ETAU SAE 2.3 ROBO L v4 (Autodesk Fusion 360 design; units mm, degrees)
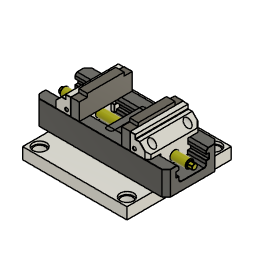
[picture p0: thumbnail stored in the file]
base_feature "Base Feature1" OffsetX 0 OffsetY 0 OffsetZ 0 OffsetX 0 OffsetY 0 OffsetZ 0 OffsetX 0 OffsetY 0 OffsetZ 0 OffsetX 0 OffsetY 0 OffsetZ 0
base_feature "Base Feature1" OffsetX 0 OffsetY 0 OffsetZ 0 OffsetX 0 OffsetY 0 OffsetZ 0 OffsetX 0 OffsetY 0 OffsetZ 0 OffsetX 0 OffsetY 0 OffsetZ 0
work_plane "WorkPlane2" User Parameter 100 named "Ouverture"
base_feature "Base Feature1"
position "Position1"
sketch "Sketch1" plane through (9.1729, 31.8972, 315) normal (1, 0, 0) x axis (0, 1, 0)
work_axis "WorkAxis1"
work_point "WorkPoint1"
joint_origin "JointOrigin7" OffsetX 0 OffsetY 0 OffsetZ 0
work_point "WorkPoint2"
work_point "WorkPoint1"
position "Position2"
position "Position3"
joint_origin "JointOrigin8" OffsetX 0 OffsetY 0 OffsetZ 0
position "Position4"
ground "Terre5"
position "Position5"
ground "Terre6"
position "Position6" TranslateAlongZ -50 (= "-Ouverture / 2") TranslateAlongZ 50 (= "Ouverture / 2")
as_built_joint "Réelle"
sketch "Esquisse1" plane through (0, 0, 0) normal (0, 0, 1) x axis (1, 0, 0)
  line L1 (-62.5, 29) -> (62.5, 29)
  line L2 (-62.5, -29) -> (-62.5, 29)
  line L3 (62.5, -29) -> (-62.5, -29)
  line L4 (62.5, 29) -> (62.5, -29)
  line L5 (-62.5, -29) -> (62.5, 29)
  line L6 (62.5, -29) -> (-62.5, 29)
  point P6 (0, 0)
  point P1 (0, 0)
  point P3 (-62.5, 29)
  point P4 (-62.5, -29)
  horizontal L1
  perpendicular L1 L2
  parallel L1 L3
  parallel L2 L4
  coincident L5 P6
  coincident L6 P6
  coincident P1 P6
  dimension "d1_1" distance P3 P4 = 58
  dimension "d2_1" distance L2 L4 = 125
extrude "Extrusion1" new body sketch "Esquisse1" profile of L1 L2 L3 L4 along normal blind 20 named "d3_1"
sketch "Esquisse2" plane through (0, -29, 0) normal (0, -1, 0) x axis (1, 0, 0)
  line L1 (62.5, 0) -> (-62.5, 0)
  line L2 (62.5, 20) -> (62.5, 0)
  line L3 (-62.5, 20) -> (62.5, 20)
  line L4 (-62.5, 0) -> (-62.5, 20)
  line L5 (-32.5, 26.5) -> (32.5, 26.5)
  line L6 (-32.5, 13.5) -> (-32.5, 26.5)
  line L7 (32.5, 13.5) -> (-32.5, 13.5)
  line L8 (32.5, 26.5) -> (32.5, 13.5)
  line L9 (-32.5, 13.5) -> (32.5, 26.5)
  line L10 (32.5, 13.5) -> (-32.5, 26.5)
  point P10 (0, 20)
  horizontal L5
  perpendicular L5 L6
  parallel L5 L7
  parallel L6 L8
  coincident L9 P10
  coincident L10 P10
  midpoint L3 P10
  dimension "d5_1" distance L6 L8 = 65
  dimension "d6_1" distance L5 L7 = 13
extrude "Extrusion2" add sketch "Esquisse2" profile of L3 L6 L7 L8 along normal blind 7 named "d7_1"
extrude "Extrusion3" cut of existing geometry blind -7
sketch "Esquisse3" plane through (0, 22, 0) normal (0, 1, 0) x axis (-1, 0, 0)
  line L1 (62.5, 0) -> (-62.5, 0)
  line L2 (62.5, 20) -> (62.5, 0)
  line L3 (-62.5, 20) -> (62.5, 20)
  line L4 (-62.5, 0) -> (-62.5, 20)
  line L5 (-43.5, 0) -> (-43.5, 20)
  line L6 (43.5, 20) -> (43.5, 0)
  point P6 (-43.5, 20)
  point P7 (-43.5, 0)
  point P8 (43.5, 0)
  point P9 (43.5, 20)
  coincident L3 P6
  coincident L1 P7
  perpendicular L1 L5
  coincident L1 P8
  coincident L3 P9
  perpendicular L3 L6
  dimension "d11" distance L4 L5 = 19
  dimension "d12" distance L2 L6 = 19
extrude "Extrusion4" cut sketch "Esquisse3" against normal blind 11
sketch "Esquisse4" plane through (0, 0, 20) normal (0, 0, 1) x axis (-1, 0, 0)
  line L1 (-43.5, -11) -> (-62.5, -11)
  line L2 (-43.5, -22) -> (-43.5, -11)
  line L3 (43.5, -22) -> (-43.5, -22)
  line L4 (43.5, -11) -> (43.5, -22)
  line L5 (62.5, -11) -> (43.5, -11)
  line L6 (62.5, 29) -> (62.5, -11)
  line L7 (32.5, 29) -> (62.5, 29)
  line L8 (32.5, 36) -> (32.5, 29)
  line L9 (-32.5, 36) -> (32.5, 36)
  line L10 (-32.5, 29) -> (-32.5, 36)
  line L11 (-62.5, 29) -> (-32.5, 29)
  line L12 (-62.5, -11) -> (-62.5, 29)
  line L13 (-62.5, 8.3) -> (62.5, 8.3)
  circle C1 centre (35.175, 8.3) radius 3.4
  circle C2 centre (-35.175, 8.3) radius 3.4
  point P14 (62.5, 8.3)
  point P15 (-62.5, 8.3)
  point P16 (35.175, 8.3)
  point P17 (-35.175, 8.3)
  point P18 (0, 8.3)
  point P19 (35.175, 8.3)
  point P20 (-35.175, 8.3)
  coincident L6 P14
  perpendicular L6 L13
  coincident L12 P15
  coincident L13 P16
  coincident L13 P17
  midpoint L13 P18
  coincident P16 P19
  coincident P17 P20
  dimension "d15_1" distance L7 L13 = 20.7
  dimension "d16_1" distance P16 P18 = 35.175
  dimension "d17_1" distance P16 P17 = 70.35
  dimension "d18_1" diameter C1 = 6.8
  dimension "d19_1" diameter C2 = 6.8
extrude "Extrusion5" cut sketch "Esquisse4" profile of L13 C1 C2 against normal blind 10 named "d20_1"
copy_paste_bodies "Copier/Coller des corps"
move "Déplacer1"
sketch "Esquisse5" plane through (0, 0, 0) normal (1, 0, 0) x axis (0, 1, 0)
sketch "Esquisse6" plane through (0, 22, 0) normal (0, 1, 0) x axis (-1, 0, 0)
  line L1 (-43.5, 0) -> (-43.5, 20)
  line L2 (43.5, 0) -> (-43.5, 0)
  line L3 (43.5, 20) -> (43.5, 0)
  line L4 (-43.5, 20) -> (43.5, 20)
sketch "Esquisse7" plane through (0, 22, 0) normal (0, 1, 0) x axis (-1, 0, 0)
  line L1 (43.5, 50) -> (43.5, 30)
  line L2 (-43.5, 50) -> (43.5, 50)
  line L3 (-43.5, 30) -> (-43.5, 50)
  line L4 (43.5, 30) -> (-43.5, 30)
sketch "Esquisse8" plane through (0, 11, 0) normal (0, 1, 0) x axis (-1, 0, 0)
  line L1 (-62.5, 0) -> (-62.5, 20)
  line L2 (-43.5, 0) -> (-62.5, 0)
  line L3 (-43.5, 20) -> (-43.5, 0)
  line L4 (-62.5, 20) -> (-43.5, 20)
sketch "Esquisse9" plane through (0, 11, 0) normal (0, 1, 0) x axis (-1, 0, 0)
  line L1 (62.5, 20) -> (62.5, 0)
  line L2 (43.5, 20) -> (62.5, 20)
  line L3 (43.5, 0) -> (43.5, 20)
  line L4 (62.5, 0) -> (43.5, 0)
sketch "Esquisse10" plane through (43.5, 0, 0) normal (1, 0, 0) x axis (0, 1, 0)
  line L1 (22, 20) -> (22, 0)
  line L2 (11, 20) -> (22, 20)
  line L3 (11, 0) -> (11, 20)
  line L4 (22, 0) -> (11, 0)
  line L5 (11, 50.006) -> (11, 0)
  point P5 (11, 0)
  point P6 (11, 0)
  coincident P5 P6
  perpendicular L4 L5
sketch "Esquisse11" plane through (-43.5, 0, 0) normal (-1, 0, 0) x axis (0, -1, 0)
  line L1 (-22, 0) -> (-22, 20)
  line L2 (-11, 0) -> (-22, 0)
  line L3 (-11, 20) -> (-11, 0)
  line L4 (-22, 20) -> (-11, 20)
  line L5 (-11, 50.0107) -> (-11, 0)
  point P4 (-11, 0)
  point P6 (-11, 0)
  coincident P4 P6
  perpendicular L2 L5
work_plane "Plan de construction1"
work_plane "Plan de construction2"
work_point "WorkPoint1"
sketch "Esquisse12" plane through (0, 0, 20) normal (0, 0, 1) x axis (-1, 0, 0)
  line L1 (-43.5, -11) -> (-62.5, -11)
  line L2 (-43.5, -22) -> (-43.5, -11)
  line L3 (43.5, -22) -> (-43.5, -22)
  line L4 (43.5, -11) -> (43.5, -22)
  line L5 (62.5, -11) -> (43.5, -11)
  line L6 (62.5, 29) -> (62.5, -11)
  line L7 (32.5, 29) -> (62.5, 29)
  line L8 (32.5, 36) -> (32.5, 29)
  line L9 (-32.5, 36) -> (32.5, 36)
  line L10 (-32.5, 29) -> (-32.5, 36)
  line L11 (-62.5, 29) -> (-32.5, 29)
  line L12 (-62.5, -11) -> (-62.5, 29)
  circle C1 centre (35.175, 8.3) radius 3.4
  circle C2 centre (-35.175, 8.3) radius 3.4
work_axis "Axe de construction1"
work_axis "Axe de construction2"
sketch "Esquisse13" plane through (0, 0, 20) normal (0, 0, 1) x axis (-1, 0, 0)
  line L1 (-43.5, -11) -> (-62.5, -11)
  line L2 (-43.5, -22) -> (-43.5, -11)
  line L3 (43.5, -22) -> (-43.5, -22)
  line L4 (43.5, -11) -> (43.5, -22)
  line L5 (62.5, -11) -> (43.5, -11)
  line L6 (62.5, 29) -> (62.5, -11)
  line L7 (32.5, 29) -> (62.5, 29)
  line L8 (32.5, 36) -> (32.5, 29)
  line L9 (-32.5, 36) -> (32.5, 36)
  line L10 (-32.5, 29) -> (-32.5, 36)
  line L11 (-62.5, 29) -> (-32.5, 29)
  line L12 (-62.5, -11) -> (-62.5, 29)
  circle C1 centre (35.175, 8.3) radius 3.4
  circle C2 centre (-35.175, 8.3) radius 3.4
work_plane "Plan de construction3"
sketch "Esquisse14" plane through (0, 0, 20) normal (0, 0, 1) x axis (-1, 0, 0)
work_point "WorkPoint2" sketch "Esquisse13"
sketch "Esquisse15" plane through (0, 0, 20) normal (0, 0, 1) x axis (-1, 0, 0)
  line L1 (0, -15) -> (0, 33)
  circle C1 centre (42, 8.2984) radius 3.35
  circle C2 centre (-42, 8.2984) radius 3.35
  point P2 (42, 8.2984)
  point P3 (-42, 8.2984)
  dimension "d22" distance P2 L1 = 42
  dimension "d23" distance P3 L1 = 42
  dimension "d24" diameter C1 = 6.7
  dimension "d25" diameter C2 = 6.7
extrude "Extrusion6" cut sketch "Esquisse15" profile of C1 C2 against normal blind 12
component_from_bodies "Corps->Comp1"
component_from_bodies "Corps->Comp2"
copy_paste "CutPaste1"
copy_paste "CutPaste2"
remove_instance "RemoveInstance1"
remove_body "RemoveBody1"
position "Position8"
copy_paste_bodies "CutPasteBodies1"
copy_paste_bodies "CutPasteBodies2"
remove_instance "RemoveInstance1"
remove_instance "RemoveInstance2"
move "Déplacer1"
remove_body "RemoveBody2"
joint "Assembler7" alignOffsetX 0 alignOffsetY 0 alignOffsetZ -55 (= "-Ouverture / 2 - 5 mm")
joint "Assembler8" alignOffsetX 0 alignOffsetY 0 alignOffsetZ 55 (= "Ouverture / 2 + 5 mm")
offset_faces "DécalerLesFaces" distance -2.7984 (= "-11.2984 mm + 8.5 mm")
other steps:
base_feature "Fonction de base1"
base_feature "Fonction de base1"
base_feature "Fonction de base2"
base_feature "Fonction de base3"
base_feature "Fonction de base1"
create_component "CreateComponent1"
create_component "CreateComponent1"
create_component "CreateComponent2"
create_component "CreateComponent2"
create_component "CreateComponent4"
create_component "CreateComponent1"
remove_body "RemoveBody1"
create_component "CreateComponent2"
remove_body "RemoveBody2"
remove_instance "RemoveInstance1"
remove_instance "RemoveInstance2"
remove_body "RemoveBody1"
remove_body "RemoveBody1"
